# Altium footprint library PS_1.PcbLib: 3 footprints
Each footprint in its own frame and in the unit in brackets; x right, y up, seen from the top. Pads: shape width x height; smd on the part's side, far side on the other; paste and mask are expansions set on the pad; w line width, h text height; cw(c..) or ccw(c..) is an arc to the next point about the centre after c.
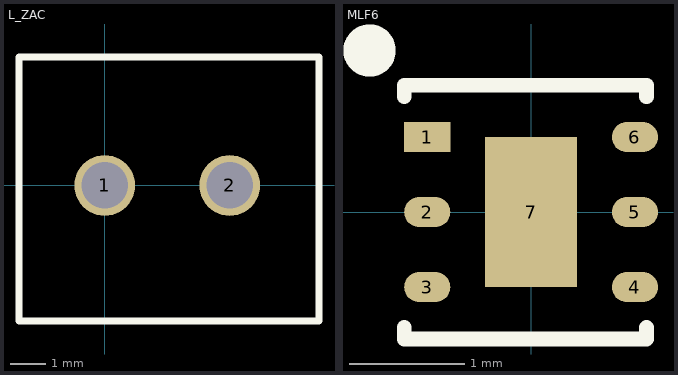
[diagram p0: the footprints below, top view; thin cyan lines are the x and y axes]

## L_ZAC [mm]
pads (2):
  round 1.7 hole 1.3: 1(0,0) 2(3.5,0)
Top Overlay:
  lines w0.2: -2.4,-3.8 6,-3.8 6,3.6 -2.4,3.6 -2.4,-3.8
3D body: height 8.5, standoff -4, extent -2.2,-3.6 5.8,3.4

## MLF6 [mm]
pads (7):
  rect 0.4x0.26 smd: 1(-0.9,0.65)
  oval 0.4x0.26 smd: 2(-0.9,0) 3(-0.9,-0.65) 4(0.9,-0.65) 5(0.9,0) 6(0.9,0.65)
  rect 0.8x1.3 smd: 7(0,0)
Top Overlay:
  circle w0.254: c-1.4,1.4 r0.1
  lines w0.127: -1.1,-1 -1.1,-1.1 1,-1.1 1,-1 ; -1.1,1 -1.1,1.1 1,1.1 1,1
3D body: height 0.65, standoff 0, extent -1,-1 1,1

## PCBComponent_1 [mm]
